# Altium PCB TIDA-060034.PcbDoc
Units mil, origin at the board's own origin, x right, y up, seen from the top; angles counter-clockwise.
Board outline 5629.92 x 147.64 mil, 2 copper layers (Top Layer, Bottom Layer), stack 4.4 mil thick; 12 components, 7 nets, 29 pads, 6 vias.
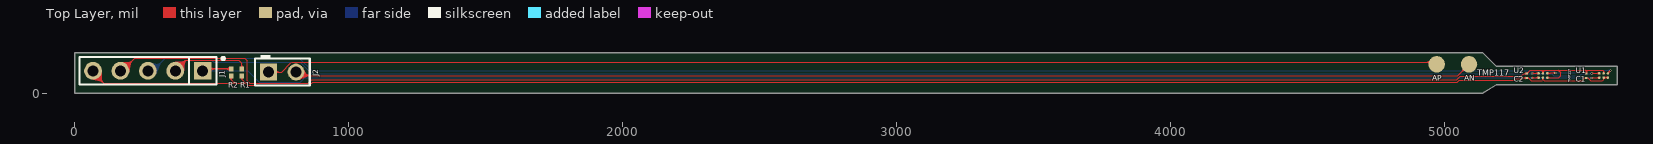
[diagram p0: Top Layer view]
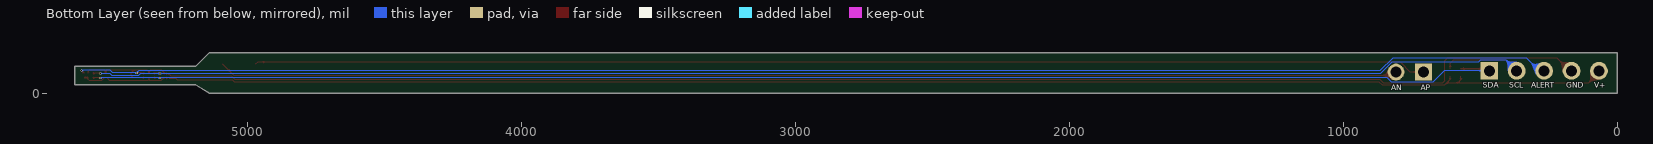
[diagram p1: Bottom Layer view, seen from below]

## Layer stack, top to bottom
Top Solder: solder mask 1, Polymide, Dk 3.3
Top Layer: signal copper 0.7
Flex Substrate: core 3, Polymide, Dk 3.3
Bottom Layer: signal copper 0.7
Bottom Solder: solder mask 1, Polymide, Dk 3.3

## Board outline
5629.92,98.33 5187.01,98.43 5137.8,147.64 0,147.64 0,0 5137.8,0 5187.01,29.53 5629.92,29.53

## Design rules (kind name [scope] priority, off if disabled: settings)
AcuteAngle [All] p1: minimum=4.50000000000000E+0001 checktracksonly=FALSE
AssemblyTestPointUsage [All] p1: valid=2
BoardOutlineClearance BoardOutlineClearance_MountingHoles [OnCopper and InComponentClass('Mounting Holes')] p1: gap=39.37 ignorepadtopadclearanceinfootprint=FALSE
BoardOutlineClearance BoardOutlineClearance_Poly [OnCopper and IsPoly] p2: gap=25 ignorepadtopadclearanceinfootprint=FALSE
BoardOutlineClearance [OnCopper and Not InComponentClass('Logo') and not InComponentClass('FiducialMark') and not InRegion(1000,500,4000,800) and not InPoly] p3: gap=10 ignorepadtopadclearanceinfootprint=FALSE
Clearance Clearance_Keepouts [((IsTrack Or IsArc) And Not InPoly) And IsFree and IsKeepOut vs ((IsTrack Or IsArc) And Not InPoly) And IsFree and IsKeepOut] p1: gap=0 ignorepadtopadclearanceinfootprint=FALSE
Clearance Clearance_Poly [InPolygon] p2: gap=25 ignorepadtopadclearanceinfootprint=TRUE
Clearance Clearance_FiducialMark [IsKeepOut and InComponentClass('FiducialMark') vs IsPad and InComponentClass('FiducialMark')] p3: gap=0 ignorepadtopadclearanceinfootprint=FALSE
Clearance [All] p4: gap=4 ignorepadtopadclearanceinfootprint=TRUE
ComponentClearance ComponentClearance_MountingHoles_FiducialMarks [InComponentClass('Mounting Holes') vs InComponentClass('FiducialMark')] p1: gap=50 collisioncheckmode=3 verticalgap=10 showdistances=FALSE
ComponentClearance ComponentClearance_Shunt [InComponentClass('Header') vs InComponentClass('Shunt')] p2: gap=0 collisioncheckmode=3 verticalgap=0 showdistances=FALSE
ComponentClearance ComponentClearance_Logo [InComponentClass('Logo')] p3: gap=50 collisioncheckmode=3 verticalgap=10 showdistances=FALSE
ComponentClearance ComponentClearance_ScrewToNut [(HasFootprint('NY PMS 440 0025 PH')) vs (HasFootprint('Keystone_1902C'))] p4: gap=5 collisioncheckmode=3 verticalgap=10 showdistances=FALSE
ComponentClearance ComponentClearance_MountingHoles [InComponentClass('Mounting Holes')] p5: gap=250 collisioncheckmode=3 verticalgap=100000 showdistances=FALSE
ComponentClearance ComponentClearance_SmallPassives [HasFootprint('0201*') or HasFootprint('0402*') or HasFootprint('0508') or HasFootprint('0603*') or HasFootprint('0612') or HasFootprint('0805*') or HasFootprint('0815*') or HasFootprint('0830*') or HasFootprint('1206*') or HasFootprint('1210*') or HasFootprint('1808*') or HasFootprint('1812*') or HasFootprint('1825*') or HasFootprint('2010*') or HasFootprint('2220*') or HasFootprint('2225*') or HasFootprint('2512*') or HasFootprint('2728*') or HasFootprint('3518*') vs HasFootprint('0201*') or HasFootprint('0402*') or HasFootprint('0508') or HasFootprint('0603*') or HasFootprint('0612') or HasFootprint('0805*') or HasFootprint('0815*') or HasFootprint('0830*') or HasFootprint('1206*') or HasFootprint('1210*') or HasFootprint('1808*') or HasFootprint('1812*') or HasFootprint('1825*') or HasFootprint('2010*') or HasFootprint('2220*') or HasFootprint('2225*') or HasFootprint('2512*') or HasFootprint('2728*') or HasFootprint('3518*')] p6: gap=14.96 collisioncheckmode=3 verticalgap=10 showdistances=FALSE
ComponentClearance ComponentClearance_THtoSMT [IsThruComponent vs IsSMTComponent] p7: gap=40 collisioncheckmode=3 verticalgap=30 showdistances=FALSE
ComponentClearance ComponentClearance_THtoTH [IsThruComponent vs IsThruComponent] p8: gap=30 collisioncheckmode=3 verticalgap=30 showdistances=FALSE
ComponentClearance [All] p9: gap=10 collisioncheckmode=3 verticalgap=10 showdistances=FALSE
DiffPairsRouting [All] p1: maxlimit=100 minlimit=10 mostfreqgap=10 toplayer_minwidth=15 toplayer_maxwidth=15 toplayer_prefwidth=15 bottomlayer_minwidth=15 bottomlayer_maxwidth=15 bottomlayer_prefwidth=15 maxuncoupledlength=1000
FabricationTestPointUsage TestPointUsage [All] p1: valid=2 allowmultiple=FALSE
FabricationTestpoint Testpoint [All] p1: side=3 testpointundercomponent=TRUE minsize=40 maxsize=100 preferedsize=60 minholesize=0 maxholesize=40 preferedholesize=32 testpointgrid=1 allowsidetop=TRUE allowsidebottom=TRUE usegrid=TRUE gridtolerance=0.01
FanoutControl Fanout_LCC [IsLCC] p1: bgadir=Out bgaviamode=Centered fanoutstyle=Auto fanoutdirection=Alternating viagrid=1 // Fanout_LCC (Default Rule)
FanoutControl Fanout_BGA [IsBGA] p2: bgadir=Out bgaviamode=Centered fanoutstyle=Auto fanoutdirection=Alternating viagrid=1 // Fanout_BGA (Default Rule)
FanoutControl Fanout_Default [All] p4: bgadir=Out bgaviamode=Centered fanoutstyle=Auto fanoutdirection=Alternating viagrid=1 // Fanout_Default (Default Rule)
FanoutControl Fanout_Small [(CompPinCount < 5)] p5: bgadir=Out bgaviamode=Centered fanoutstyle=Auto fanoutdirection=OutThenIn viagrid=1 // Fanout_Small (Default Rule)
HoleSize [All] p1: absolutevalues=TRUE maxlimit=251 minlimit=4 maxpercent=80.000 minpercent=20.000
MinimumAnnularRing MinimumAnnularRing_ThermalPadVias [IsVia and InAnyComponent] p1: minimumring=5.91
MinimumAnnularRing [All] p2: minimumring=2
MinimumSolderMaskSliver MinimumSolderMaskSliver_Logo [InComponentClass('Logo') vs InComponentClass('Logo')] p1: minsoldermaskwidth=0.7
MinimumSolderMaskSliver [All] p2: minsoldermaskwidth=3.94
PlaneConnect [All] p1: planeconnectstyle=Relief reliefexpansion=10 reliefentries=4 reliefconductorwidth=10 reliefairgap=10
PolygonConnect [All] p1: connectstyle=Relief reliefconductorwidth=10 reliefentries=4 polygonreliefangle="90 Angle" airgapwidth=10
RoutingVias ThermalPadVias [IsVia and InAnyComponent] p1: holewidth=7.87 width=19.68 viastyle="Through Hole" minholewidth=7.87 minwidth=19.68 maxholewidth=12.99 maxwidth=23.62
RoutingVias [All] p2: holewidth=6 width=12 viastyle="Through Hole" minholewidth=4 minwidth=8 maxholewidth=15 maxwidth=24
SilkToBoardRegionClearance [Not ((IsComment or IsDesignator) And (Hide <> 'False')) and not InRegion(1000,500,4000,800)] p1:
SilkToSilkClearance SilkToSilkClearance_Pb-FreeLogo [(HasFootprint('Pb-Free_Overlay_Medium') OR HasFootprint('Pb-Free_Overlay_Small')) vs (HasFootprint('Pb-Free_Overlay_Medium') OR HasFootprint('Pb-Free_Overlay_Small'))] p1: silktosilkclearance=0
SilkToSilkClearance [All] p2: silktosilkclearance=3.94
SilkToSolderMaskClearance SilkToComponentPadClearance [(IsPad or IsFill or IsRegion) and InAnycomponent] p1: minsilkscreentomaskgap=5 clearancetoexposedcopper=TRUE
SilkToSolderMaskClearance "Silk to Solder Mask Opening" [All] p2: minsilkscreentomaskgap=3.94 clearancetoexposedcopper=FALSE
SolderMaskExpansion SolderMaskExpansion_1 [IsVia] p1: expansion=-20
SolderMaskExpansion [All] p2: expansion=1.97
UnRoutedNet [All] p1: checkbadconnections=TRUE
Width [All] p1: maxlimit=6 minlimit=4 preferedwidth=6 checkconnectedcopper=TRUE
14 further rules are at their usual default settings.

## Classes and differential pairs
component class Header: J1
component class AssemblyNote: ZZ1 ZZ2 ZZ3 ZZ4

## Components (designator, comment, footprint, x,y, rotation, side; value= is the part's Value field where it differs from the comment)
C1 "GRM022R60J104ME15" 01005 5516.54,62.99 r90 top value=0.1uF
C2 "GRM022R60J104ME15" 01005 5299.21,62.99 r90 top value=0.1uF
J1 "HTSW-105-07-G-S" Samtec_HTSW-105-07-G-S 267.32,81.13 r180 top
J2 "HTSW-102-09-G-S" Samtec_HTSW-102-09-x-S 757.87,76.77 r0 top
R1 "RC0201JR-075K1L" 0201 610.24,75.17 r270 top value=5.1k
R2 "RC0201JR-075K1L" 0201 570.87,75.17 r270 top value=5.1k
U1 "TMP117AIYBGR" YBG0006AJAP 5579.72,64 r90 top
U2 "TMP117AIYBGR" YBG0006AJAP 5358.27,64 r90 top
ZZ1 "This Assembly Note is for PCB labels only" AssemblyNoteLabel 185,3938 r0 top
ZZ2 "These assemblies are ESD sensitive, ESD precautions shall be observed." AssemblyNote 185,3829.11 r0 top
ZZ3 "These assemblies must be clean and free from flux and all contaminants. Use of no clean flux is not acceptable." AssemblyNote 185,3740.56 r0 top
ZZ4 "These assemblies must comply with workmanship standards IPC-A-610 Class 2, unless otherwise specified." AssemblyNote 185,3652 r0 top

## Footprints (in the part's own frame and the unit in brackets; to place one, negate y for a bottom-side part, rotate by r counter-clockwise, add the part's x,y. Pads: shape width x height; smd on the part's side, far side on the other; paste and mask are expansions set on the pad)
0201 [mm] "Data from Kemet datasheet CC101_COM dated 7/28/11"
  rect 0.46x0.42 smd mask+0.048: 1(-0.33,0) 2(0.33,0)
  body extent -0.31,-0.16 0.31,0.16, height 0.26
01005 [mm] "Metric 0402"
  rect 0.2x0.2 smd: 1(-0.2,0) 2(0.2,0)
  body extent -0.21,-0.11 0.21,0.11, height 0.2
AssemblyNote [mil] "Assembly Note"
AssemblyNoteLabel [mil] "Assembly Note for PCB Labels"
Samtec_HTSW-102-09-x-S [mm] "Header, 2x1, 2.54mm, TH"
  rect 1.55x1.55 hole 1.02: 1(-1.27,0)
  round 1.55 hole 1.02: 2(1.27,0)
  silkscreen extent -2.54,-1.24 2.54,1.6, body extent -2.54,-1.24 2.54,1.24, height 8.38
Samtec_HTSW-105-07-G-S [mm] "Samtec 100mil, 1x5, 230 mil above insulator"
  rrect6% 1.65x1.65 hole 1.016: 1(-5.08,0)
  round 1.65 hole 1.016: 2(-2.54,0) 3(0,0) 4(2.54,0) 5(5.08,0)
  silkscreen extent -7.11,-1.27 6.35,1.27, body extent -6.35,-1.27 6.35,1.27, height 8.38
YBG0006AJAP [mm] "DSBGA-6"
  round 0.23 smd paste-0.23 mask+0.032: A1(-0.2,0.4) A2(0.2,0.4) B1(-0.2,0) B2(0.2,0) C1(-0.2,-0.4) C2(0.2,-0.4)
  body extent -0.61,-0.81 0.62,0.82, height 0.5

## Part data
C1 C2: library part CMP-0009442-2, "CAP, CERM, 0.1 uF, 6.3 V, +/- 20%, X5R, 01005", Cap_Case=01005, Manufacturer=MuRata, TempCo=X5R, Tolerance_%=20%, Value1=Unknown, Value2=6.3V, ValueDisplayed=0.1uF
J1: library part CMP-0075485-1, "Header, 100mil, 5x1, Gold, TH", Manufacturer=Samtec, Supplier Part Number 1=SAM8737-ND
J2: library part CMP-0075626-1, "Header, 100mil, 2x1, Gold, TH", Color=Black, Manufacturer=Samtec
R1 R2: library part CMP-0027144-1, "RES, 5.1 k, 5%, 0.05 W, 0201", Manufacturer="Yageo America", Power_W=50mW, Supplier Part Number 1=YAG2910CT-ND, TempCo="200 ppm/C", Tolerance_%=5%, Value2=0.05W, Value_Code=5k10, ValueDisplayed=5.1k
U1 U2: library part CMP-0860099-1, "±0.1°C accurate digital temperature sensor with integrated NV memory, YBG0006AJAP (DSBGA-6)", Alternate Manufacturer="Texas Instruments", Alternate PartNumber=TMP117AIYBGT, Operating Temperature Range="-55 to 150,0 to 85 C", Rating=Catalog
ZZ1: library part CMP-0003616-3
ZZ2: library part CMP-0077236-1
ZZ3: library part CMP-0077237-1
ZZ4: library part CMP-0077238-1

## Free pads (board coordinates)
  round 60 smd mask-5: 1(4970.47,105) 1(5088.58,105)

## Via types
v1: diameter 8, hole 4, Top Layer to Bottom Layer, 6 vias

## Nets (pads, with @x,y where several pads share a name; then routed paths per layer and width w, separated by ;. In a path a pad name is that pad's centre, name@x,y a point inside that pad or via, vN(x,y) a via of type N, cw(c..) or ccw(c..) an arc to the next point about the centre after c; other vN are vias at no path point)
ALERT: J1.3 U1.C2 U2.C2 | length 5428.6
  Top Layer w4: U2.C2 5384.49,71.87 5386.12,73.5 v1(5403.54,73.5) ; v1@5403.18,71.87 v1@5403.54,72.24 ; U1.C2@5595.47,72.24 5595.47,73.12 v1(5605.13,82.77)
  Bottom Layer w4: J1.3 273.9,87.71 291.23,87.71 331.13,127.61 819.99,127.61 866.35,81.24 5395.8,81.24 v1(5403.54,73.5) 5491.51,73.5 5500.78,82.77 v1(5605.13,82.77)
AN: J2.2 pad.1@5088.58,105 | length 4315.2
  Top Layer w4: J2.2@816.58,85.48 J2.2 820.52,64.13 5047.71,64.13 pad.1@5088.58,105
AP: J2.1 pad.1@4970.47,105 | length 4281.2
  Top Layer w4: J2.1 755.91,76.77 789.02,109.89 789.35,109.89 792.75,113.28 4962.19,113.28 pad.1@4970.47,105
GND: C1.2 C2.2 J1.4 U1.B2 U2.B2 U2.C1 | length 5642
  Top Layer w4: J1.4@167.32,75.17 220.1,127.95 620.08,127.95 629.92,118.11 629.92,45.28 639.43,35.77 852.7,35.77 865.18,48.25 5043.15,48.25 5055.9,61 5277.94,61 5287.81,70.86 C2.2 5300.2,70.86 5311.73,82.4 5353.92,82.4 5358.27,78.06 ; U2.B2 5358.27,78.06 ; U2.C1 5415.85,56.13 5423.23,63.5 5423.23,74.12 5413.39,83.96 ; C1.2 5516.54,79.32 ; U1.B2@5579.72,72.24 5579.72,79.32 5576.27,82.77 5519.99,82.77 5516.54,79.32 ; 5358.27,78.06 5364.17,83.96 5413.39,83.96 ; 5413.39,83.96 5511.9,83.96 5516.54,79.32
SCL: J1.2 R1.1 U1.A2 U2.A2 | length 5547
  Top Layer w4: J1.2 405.8,119.61 598.9,119.61 610.24,108.27 R1.1 ; v1(5318.9,71.24) 5319.53,71.87 U2.A2 ; v1(5536.23,71.24) 5537.23,72.24 U1.A2@5563.98,72.24
  Bottom Layer w4: J1.2 405.8,119.61 501.15,119.61 507.47,113.28 823,113.28 865.04,71.24 v1(5318.9,71.24) 5390.4,71.24 5398.14,63.5 5492.82,63.5 5500.56,71.24 v1(5536.23,71.24)
SDA: J1.1 R2.1 U1.A1 U2.A1 | length 5252.8
  Top Layer w4: v1(5318.9,55.49) 5319.53,56.13 U2.A1 ; v1(5536.23,55.49) U1.A1@5563.98,55.49
  Top Layer w6: J1.1 474.36,88.17 R2.1
  Bottom Layer w4: J1.1 632.6,81.13 674.46,39.26 823.41,39.26 839.65,55.49 v1(5318.9,55.49) v1(5536.23,55.49) v1@5534.98,54.24
VCC: C1.1 C2.1 J1.5 R1.2 R2.2 U1.B1 U1.C1 U2.B1 | length 5651.8
  Top Layer w4: J1.5@67.32,75.17 105.8,36.69 583.39,36.69 ; R2.2 570.87,49.21 583.39,36.69 ; R1.2 610.24,50.1 623.65,36.69 ; U2.B1 5358.27,49.59 ; U1.B1@5579.72,55.49 5579.72,49.18 5575.51,44.97 5532.61,44.97 5522.46,55.12 C1.1 5510.71,55.12 5501.09,45.49 5362.36,45.49 5358.27,49.59 ; U1.B1@5579.72,56.49 U1.C1@5595.47,56.49 ; 583.39,36.69 623.65,36.69 ; 623.65,36.69 632.57,27.77 856.01,27.77 868.5,40.25 5046.46,40.25 5052.6,46.39 5252.67,46.39 5259.28,53 5283.1,53 5285.21,55.12 C2.1 5305.13,55.12 5314.76,45.49 5355.51,45.49 5358.27,48.25 5358.27,49.59

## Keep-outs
Keep-Out Layer:
  text ".Layer_Name" at 577,-858.49 h60

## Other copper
Top Layer:
  text ".Layer_Name" at 577,-858.49 h60
Bottom Layer:
  text ".Layer_Name" at 577,-858.49 h60

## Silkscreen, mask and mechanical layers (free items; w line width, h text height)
Top Overlay:
  text "TMP117" at 5118.11,55.49 h37
  text "AP" at 4953.81,44.97 h20
  text "AN" at 5071.92,44.97 h20
  text "TMP117" at 5462.6,39.79 h15 r90
  text ".Layer_Name" at 577,-858.49 h60
Bottom Overlay:
  text "V+" at 83.98,19.68 h20
  text "GND" at 187.01,19.68 h20
  text "ALERT" at 313.97,19.68 h20
  text "SCL" at 393.7,19.68 h20
  text "SDA" at 492.13,19.68 h20
  text "AP" at 717.72,9.84 h20
  text "AN" at 825.98,9.84 h20
  text ".Layer_Name" at 577,-858.49 h60
Top Paste:
  text ".Layer_Name" at 577,-858.49 h60
Bottom Paste:
  text ".Layer_Name" at 577,-858.49 h60
Top Solder:
  text ".Layer_Name" at 577,-858.49 h60
  text ".Layer_Name" at 577,-858.49 h60
Bottom Solder:
  text ".Layer_Name" at 577,-858.49 h60
Drill Guide:
  text ".Layer_Name" at 577,-858.49 h60
M1 Board Outline:
  lines w10: 5629.83,29.53 5187.01,29.53 5137.8,0 0,0 0,147.64 5137.8,147.64 5186.83,98.13 5629.83,98.5 5629.83,31.97
  text ".Layer_Name" at 577,-858.49 h60
M2 Board Dimensions:
  rectangle: 0,-275 125,-150
  rectangle: 125,-400 500,-275
  lines w7: 0,-275 1000,-275 ; 125,-400 125,-150 ; 250,-400 250,-150 ; 500,-400 500,-150 ; 750,-400 750,-150 ; 0,-400 1000,-400 1000,-150 0,-150 0,-400
  text ".Layer_Name" at 577,-858.49 h60
M3 3D STEP Top:
  text ".Layer_Name" at 577,-858.49 h60
M4 3D STEP Bottom:
  text ".Layer_Name" at 577,-858.49 h60
M5 Assembly Top:
  lines w10: -292,-930.17 6308,-930.17 ; -292,-726.83 6310,-726.83 ; -292,-523.5 -292,-1133.5 3713,-1133.5 6310,-1133.5 6310,-523.5 -291.5,-523.5 -291.5,-1133.5 1284,-1133.5 ; 2173,-1133.5 2173,-523.5 ; 3440,-726.83 3440,-523.5 ; 4280,-726.83 4280,-523.5 ; 4902,-1140 4902,-937.17
  text "COMPONENTS MARKED 'DNP' SHOULD NOT BE POPULATED." at 1153.5,-318.5 h60
  text "ASSEMBLY VARIANT:" at 1153,-434 h60
  text ".VariantName" at 2189,-434 h60
  text "PCB VIEWED FROM TOP SIDE" at -228.5,-655.67 h60
  text "BOARD #:" at 2248,-655.67 h60
  text ".PRJ_Number" at 2793.5,-655.67 h60
  text "REV:" at 3638,-655.67 h60
  text ".PCB_Rev" at 3929.5,-655.67 h60
  text "SVN REV:" at 4476,-655.67 h60
  text ".VersionControl_RevNumber" at 4982,-655.67 h60
  text "TID #:" at 2248,-859 h60
  text ".TID" at 2793.5,-859 h60
  text "PLOT NAME =" at -228.5,-1064.34 h60
  text ".plot_File_Name" at 577,-1064.34 h60
  text "GENERATED    :" at 2250,-1064.34 h60
  text ".Print_Date" at 3119.5,-1064.34 h60
  text ".Print_Time" at 3848.5,-1064.34 h60
  text "TEXAS INSTRUMENTS" at 5113,-1064.34 h60
M6 Assembly Bottom:
  lines w10: -292.5,-727.33 6309.5,-727.33 ; -290.5,-930.67 6309.5,-930.67 ; 1115.5,-1140.5 1115.5,-937.67 ; 1737.5,-727.33 1737.5,-524 ; 2577.5,-727.33 2577.5,-524 ; 3844.5,-1134 3844.5,-524 ; 4733.5,-1134 6309,-1134 6309,-524 -292.5,-524 -292.5,-1134 2304.5,-1134 6309.5,-1134 6309.5,-524
  text "COMPONENTS MARKED 'DNP' SHOULD NOT BE POPULATED." at 6102,-318 h60
  text ".VariantName" at 5058,-434 h60
  text "ASSEMBLY VARIANT:" at 6097,-434 h60
  text ".VersionControl_RevNumber" at 1035.5,-656.17 h60
  text "SVN REV:" at 1541.5,-656.17 h60
  text ".PCB_Rev" at 2088,-656.17 h60
  text "REV:" at 2379.5,-656.17 h60
  text ".PRJ_Number" at 3224,-656.17 h60
  text "BOARD #:" at 3769.5,-656.17 h60
  text "PCB VIEWED FROM BOTTOM SIDE" at 6246,-656.17 h60
  text ".TID" at 3224,-859.5 h60
  text "TID #:" at 3769.5,-859.5 h60
  text "TEXAS INSTRUMENTS" at 904.5,-1064.84 h60
  text ".Print_Time" at 2169,-1064.84 h60
  text ".Print_Date" at 2898,-1064.84 h60
  text "GENERATED    :" at 3767.5,-1064.84 h60
  text ".plot_File_Name" at 5440.5,-1064.84 h60
  text "PLOT NAME =" at 6246,-1064.84 h60
M9 Title Sheet:
  drawing of 57 lines, arcs and shapes, not listed
  text "1" at 739.84,8036.5 h70
  text "2" at 3235.5,8036.5 h70
  text "3" at 5724.84,8036.5 h70
  text "4" at 8231.51,8036.5 h70
  text "5" at 10730.5,8036.5 h70
  text "6" at 13235.5,8036.5 h70
  text "A" at -416.5,6893.5 h70
  text "A" at 14383.5,6893.5 h70
  text "B" at -416.5,4513.5 h70
  text "B" at 14383.5,4513.5 h70
  text "C" at -416.5,2138.5 h70
  text "C" at 14383.5,2138.5 h70
  text "PROJECT TITLE:" at 11343.5,277.5 h45
  text ".PRJ_Title" at 11393.5,144.17 h70
  text "DESIGNED FOR:" at 11343.5,-23.5 h45
  text ".PRJ_Customer" at 11393.5,-163.5 h70
  text "D" at -416.5,-231.5 h70
  text "D" at 14383.5,-231.5 h70
  text "FILE NAME:" at 11343.5,-323.5 h45
  text ".PCB_File_Name_No_Path" at 11393.5,-443.5 h70
  text "Texas Instruments (TI) and/or its licensors do not warrant the accuracy or completeness of this specification" at 6374,-605.34 h45
  text "ENGINEER:" at 11343.5,-613.5 h45
  text "LAYOUT BY:" at 12848.5,-613.5 h45
  text "or any information contained therein. TI and/or its licensors do not warrant that this design will meet" at 6329.01,-718 h45
  text ".PRJ_Engineer" at 11393.5,-768.49 h70
  text ".PCB_Layout" at 12899,-768.49 h70
  text "the specifications, will be suitable for your application or fit for any particular purpose, or will operate in" at 6329.01,-830.67 h45
  text ".Layer_Name" at 577,-858.49 h60
  text "ALTIUM DESIGNER VERSION:" at 12848.5,-923.5 h45
  text "an implementation. TI and/or its licensors do not warrant that the design is production worthy. You should" at 6329.01,-943.33 h45
  text "completely validate and test your design implementation to confirm the system functionality for your application." at 6374,-1056 h45
  text ".print_Scale" at 11393.5,-1056.83 h70
  text ".Application_BuildNumber" at 12899,-1056.83 h70
  text "1" at 739.84,-1263.5 h70
  text "2" at 3235.5,-1263.5 h70
  text "3" at 5724.84,-1263.5 h70
  text "4" at 8231.51,-1263.5 h70
  text "5" at 10730.5,-1263.5 h70
  text "6" at 13235.5,-1263.5 h70
M10 Fab Notes:
  drawing of 189 lines, arcs and shapes, not listed
  text "DESIGN INFORMATION" at 12382.02,6356.17 h60
  text "MIN. TRACK WIDTH:" at 11737.46,6224.05 h60
  text "8" at 12833.7,6224.05 h60
  text "MIL" at 12988.46,6224.05 h60
  text "MIN. CLEARANCE:" at 11737.46,6099.92 h60
  text "0.2" at 12773.7,6099.93 h60
  text "mm" at 12988.46,6099.92 h60
  text "MIN. VIA PAD SIZE:" at 11737.46,5975.8 h60
  text "24" at 12803.71,5975.8 h60
  text "MIL" at 12988.46,5975.8 h60
  text "0.05mm (2MIL)" at 12432.46,5845.9 h60
  text "MINIMUM ANNULAR RING" at 11408.23,5837.67 h60
  text "EXTERNAL" at 13140.46,5837.67 h60
  text "PER" at 11608.23,5727.55 h60
  text "IPC-D-275 CLASS 2 LEVEL C" at 11828.23,5727.54 h60
  text "MIL, HOLES" at 13316.46,5627.07 h60
  text "+/-" at 12924,5618.48 h60
  text "+/-" at 13778,5618.48 h60
  text "REGISTRATION TOLERANCES:" at 11408.23,5617.42 h60
  text "METAL" at 12608,5617.42 h60
  text "5" at 13184.2,5617.42 h60
  text "3" at 14017.2,5617.42 h60
  text "MIL" at 14133.46,5617.42 h60
  text "HOLE SIZE TOLERANCE (UNLESS OTHERWISE SPECIFIED):" at 11408.23,5519.1 h60
  text "+/-" at 13778,5516.23 h60
  text "3" at 14017.2,5515.17 h60
  text "MIL" at 14133.46,5515.17 h60
  text "MATERIAL:" at 11333.46,5377.52 h60
  text "FR-4 High Tg" at 12319.9,5249 h60
  text "Flex (Polymide)" at 13586.95,5246.33 h60
  text "FR-408" at 11754.46,5236.49 h60
  text "X" at 13061.02,5236.49 h60
  text "OTHER" at 13242.46,5236.49 h60
  text "6.4 MIL (.163mm) +/-10%" at 12074.56,5093.46 h60
  text "X" at 11954.46,5091.01 h60
  text "THICKNESS:" at 11408.23,5085.24 h60
  text "OTHER" at 13359.46,5085.24 h60
  text "TOLERANCE:" at 11408.23,4946.92 h60
  text "X" at 12256.46,4946.92 h60
  text "ANSI IPC-6012 TYPE 3 CLASS 2" at 12434.48,4946.92 h60
  text "OTHER +/-" at 12434.46,4802.73 h60
  text "BOW & TWIST:" at 11408.23,4657.54 h60
  text "X" at 12256.46,4657.54 h60
  text "ANSI IPC-6012 TYPE 3 CLASS 2" at 12434.48,4657.54 h60
  text "OTHER +/-" at 12434.46,4510.85 h60
  text "DRILLING:" at 11333.46,4380.23 h60
  text "NC_DRILL FILES" at 13094.46,4275.04 h60
  text "REFERENCE:" at 11408.23,4271.1 h60
  text "X" at 12065.46,4271.01 h60
  text "AS SHOWN" at 12243.46,4271.1 h60
  text "X" at 12966.46,4271.1 h60
  text "OTHER" at 13392.46,4128.85 h60
  text "PTH COPPER THICKNESS:" at 11407.91,4125.32 h60
  text "X" at 12547.14,4125.32 h60
  text "20-30 um" at 12675.14,4125.32 h60
  text "BOARD FINISH:" at 11333.46,3977.73 h60
  text "SILKSCREEN:" at 11488.68,3867.6 h60
  text "X" at 12446.46,3867.6 h60
  text "TOP" at 12563.46,3867.6 h60
  text "X" at 12956.46,3867.6 h60
  text "BOTTOM" at 13074.46,3867.6 h60
  text "SILKSCREEN COLOR:" at 11488.68,3712.41 h60
  text "X" at 12445.46,3712.41 h60
  text "WHITE" at 12563.46,3712.41 h60
  text "OTHER" at 13074.46,3712.41 h60
  text "X" at 12576.46,3568.96 h60
  text "GREEN" at 12694.46,3568.96 h60
  text "OTHER" at 13312.46,3568.96 h60
  text "SOLDER RESIST COLOR:" at 11488.68,3562.1 h60
  text "X" at 12576.46,3414.71 h60
  text "MATTE" at 12694.46,3414.71 h60
  text "SEMI-GLOSS" at 13312,3414.07 h60
  text "IMMERSION GOLD (ENIG)" at 12394.46,3241.94 h60
  text "ENEPIG" at 13732,3234.72 h60
  text "SURFACE FINISH:" at 11333.46,3233.72 h60
  text "X" at 12216.46,3233.72 h60
  text "IMM. TIN/SILVER OR EQUIV" at 11663,3096.4 h60
  text "OTHER" at 13094.46,3092.47 h60
  text "ARRAY/PANEL:" at 11333.46,2937.09 h60
  text "CUT AND TRIM PER M1 BOARD OUTLINE" at 12394.46,2928.87 h60
  text "N.C. ROUTE" at 12394.46,2792.9 h60
  text "X" at 13082.46,2792.9 h60
  text "V. SCORE" at 13260.46,2792.9 h60
  text "CERTIFICATION:" at 11333.46,2663.77 h60
  text "MATERIALS AND WORKMANSHIP FOR ALL PCBS" at 12058.46,2663.77 h60
  text "TO MEET OR EXCEED THE REQUIREMENTS OF:" at 12058.46,2569.71 h60
  text "X" at 11695.97,2441.08 h60
  text "ANSI IPC-A-600F CLASS ->" at 11823.96,2441.08 h60
  text "X" at 13471.97,2441.08 h60
  text "2" at 13581.96,2441.08 h60
  text "1" at 13266.96,2439.58 h60
  text "3" at 13935.96,2439.58 h60
  text "X" at 12507.97,2293.39 h60
  text "RoHS" at 12635.96,2293.39 h60
  text "OTHER" at 13280.36,2293.39 h60
  text "PER ORDER" at 13677.42,2293.39 h60
  text "ALL BOARDS MUST MEET OR EXCEED UL94-V0 REQUIREMENTS." at 11361,2139.57 h60
  text "PCB MUST BEAR THE UL94V-0 UL REGISTERED MATERIAL ID NUMBER" at 11361,2023.5 h60
  text "ADDITIONAL REQUIREMENTS:" at 11333.46,1854.08 h60
  text "MICROSECTION:" at 11408.23,1746.95 h60
  text "YES" at 12313.96,1746.95 h60
  text "REQUIRED" at 13175.46,1602.62 h60
  text "BARE BOARD ELEC. TEST:" at 11408.23,1599.76 h60
  text "NONE" at 12713.96,1599.76 h60
  text "X" at 13057.46,1599.76 h60
  text "PER ORDER" at 13767.46,1599.76 h60
  text "XX MIL VIAS REQUIRE NON-CONDUCTIVE FILL AND PLANARIZE" at 11576.38,1394.82 h59
  text "XX MIL VIAS REQUIRE CONDUCTIVE FILL AND PLANARIZE" at 11584.38,1290.84 h60
  text "OUTER XX MIL TRACES REQUIRE 50 OHM SINGLE-ENDED IMPEDANCE" at 11583.39,1127.46 h58
  text "LAYER 2 & 3 (INNER LAYERS) XX MIL WIDE, XX MIL SPACE / TRACES REQUIRE 100 OHM DIFFERENTIAL IMPEDANCE" at 11575.39,891.74 h60
  text ".Layer_Name" at 577,-858.49 h60
M11 Gerber Information:
  lines w10: -292,-930.17 6308,-930.17 ; -292,-726.83 6310,-726.83 ; -292,-523.5 -292,-1133.5 3713,-1133.5 6310,-1133.5 6310,-523.5 -291.5,-523.5 -291.5,-1133.5 1284,-1133.5 ; 2173,-1133.5 2173,-523.5 ; 3440,-726.83 3440,-523.5 ; 4280,-726.83 4280,-523.5 ; 4902,-1140 4902,-937.17
  text "ALL ARTWORK VIEWED FROM TOP SIDE" at -228.5,-655.67 h60
  text "BOARD #:" at 2248,-655.67 h60
  text ".PRJ_Number" at 2793.5,-655.67 h60
  text "REV:" at 3638,-655.67 h60
  text ".PCB_Rev" at 3929.5,-655.67 h60
  text "SVN REV:" at 4476,-655.67 h60
  text ".VersionControl_RevNumber" at 4982,-655.67 h60
  text "LAYER NAME =" at -228.5,-858.49 h60
  text "TID #:" at 2248,-859 h60
  text ".TID" at 2793.5,-859 h60
  text "PLOT NAME =" at -228.5,-1064.34 h60
  text ".plot_File_Name" at 577,-1064.34 h60
  text "GENERATED    :" at 2250,-1064.34 h60
  text ".Print_Date" at 3119.5,-1064.34 h60
  text ".Print_Time" at 3848.5,-1064.34 h60
  text "TEXAS INSTRUMENTS" at 5113,-1064.34 h60
M12 Stackup:
  drawing of 354 lines, arcs and shapes, not listed
  text "Layer" at 9811.59,7469.94 h60
  text "Name" at 10221.51,7469.94 h60
  text "Material" at 11151.25,7469.94 h60
  text "Thickness" at 11731.11,7469.94 h60
  text "Constant" at 12380.94,7469.94 h60
  text "Board Layer Stack" at 12950.81,7469.94 h60
  text "Board Layer Stack" at 14070.49,7469.94 h60
  text "Board Layer Stack" at 15190.17,7469.94 h60
  text "1" at 9811.59,7349.94 h60
  text "Top Overlay" at 10221.51,7349.94 h60
  text "2" at 9811.59,7229.94 h60
  text "Top Solder" at 10221.51,7229.94 h60
  text "Polymide" at 11151.25,7229.94 h60
  text "1.00mil" at 11731.11,7229.94 h60
  text "3.3" at 12380.94,7229.94 h60
  text "3" at 9811.59,7109.94 h60
  text "Top Layer" at 10221.51,7109.94 h60
  text "Copper" at 11151.25,7109.94 h60
  text "0.70mil" at 11731.11,7109.94 h60
  text "4" at 9811.59,6989.94 h60
  text "Flex Substrate" at 10221.51,6989.94 h60
  text "Polymide" at 11151.25,6989.94 h60
  text "3.00mil" at 11731.11,6989.94 h60
  text "3.3" at 12380.94,6989.94 h60
  text "5" at 9811.59,6869.94 h60
  text "Bottom Layer" at 10221.51,6869.94 h60
  text "Copper" at 11151.25,6869.94 h60
  text "0.70mil" at 11731.11,6869.94 h60
  text "6" at 9811.59,6749.94 h60
  text "Bottom Solder" at 10221.51,6749.94 h60
  text "Polymide" at 11151.25,6749.94 h60
  text "1.00mil" at 11731.11,6749.94 h60
  text "3.3" at 12380.94,6749.94 h60
  text "7" at 9811.59,6629.94 h60
  text "Bottom Overlay" at 10221.51,6629.94 h60
  text ".Layer_Name" at 577,-858.49 h60
M13 Component Bodies Top:
  text ".Layer_Name" at 577,-858.49 h60
M14 Component Bodies Bottom:
  text ".Layer_Name" at 577,-858.49 h60
M15 Courtyards Top:
  text ".Layer_Name" at 577,-858.49 h60
M16 Courtyards Bottom:
  text ".Layer_Name" at 577,-858.49 h60
Drill Drawing:
  circle w10: c5363.72,3273.96 r27.63
  lines w10: 5336.09,3122.02 5391.34,3122.02 5391.34,3177.27 5336.09,3177.27 5336.09,3122.02 ; 5336.09,3425.91 5391.34,3425.91 5363.72,3370.66 5336.09,3425.91
  lines w12: 5286,3084.72 8517.49,3084.72 ; 5286,3457.68 8517.49,3457.68 ; 5623.86,2960.4 5623.86,3582 ; 5955.86,2960.4 5955.86,3582 ; 6592.43,2960.4 6592.43,3582 ; 6851.57,2960.4 6851.57,3582 ; 7226.72,2960.4 7226.72,3582 ; 7951.05,2960.4 7951.05,3582 ; 5286,2960.4 8517.49,2960.4 8517.49,3582 5286,3582 5286,2960.4
  text "Symbol" at 5360.59,3494.98 h72
  text "Quantity" at 5661.16,3494.98 h72
  text "Finished Hole Size" at 5993.16,3494.98 h72
  text "Plated" at 6629.72,3494.98 h72
  text "Hole Type" at 6888.86,3494.98 h72
  text "Drill Layer Pair" at 7264.02,3494.98 h72
  text "Hole Tolerance" at 7988.35,3494.98 h72
  text "6" at 5661.16,3370.66 h60
  text "4.00mil (0.102mm)" at 5993.16,3370.66 h60
  text "PTH" at 6629.72,3370.66 h60
  text "Round" at 6888.86,3370.66 h60
  text "Top Layer - Bottom Layer" at 7264.02,3370.66 h60
  text "5" at 5661.16,3246.34 h60
  text "40.00mil (1.016mm)" at 5993.16,3246.34 h60
  text "PTH" at 6629.72,3246.34 h60
  text "Round" at 6888.86,3246.34 h60
  text "Top Layer - Bottom Layer" at 7264.02,3246.34 h60
  text "2" at 5661.16,3122.02 h60
  text "40.16mil (1.020mm)" at 5993.16,3122.02 h60
  text "PTH" at 6629.72,3122.02 h60
  text "Round" at 6888.86,3122.02 h60
  text "Top Layer - Bottom Layer" at 7264.02,3122.02 h60
  text "13 Total" at 5661.16,2997.7 h60
  text ".Layer_Name" at 577,-858.49 h60
M17 Embedded Cavity:
  text ".Layer_Name" at 577,-858.49 h60
M18 Embedded Assembly:
  text ".Layer_Name" at 577,-858.49 h60
M19 Embedded Keepout:
  text ".Layer_Name" at 577,-858.49 h60

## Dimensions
0,-400 to 1000,-400 on M2 Board Dimensions
0,0 to 0,147.64 on M2 Board Dimensions
0,0 to 5187.01,98.43 on M2 Board Dimensions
